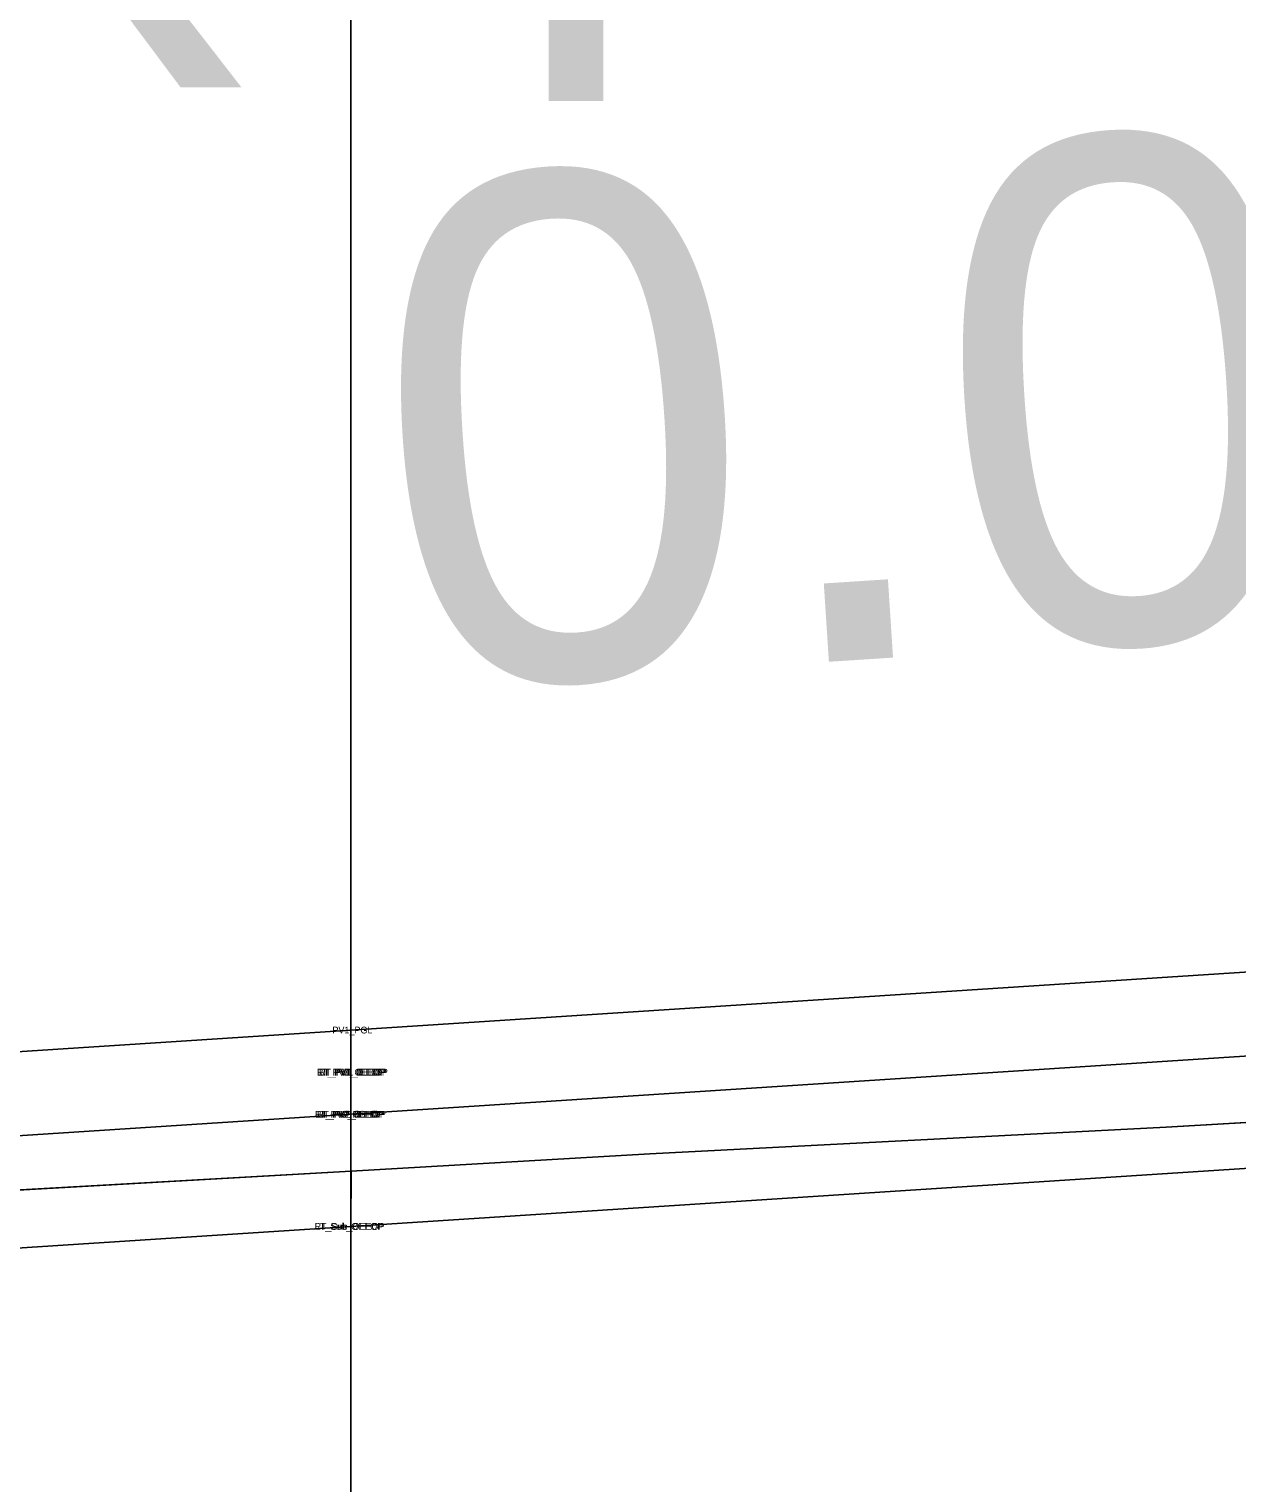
# Model space of a CAD drawing. Extents: x -26 to 403, y -376 to 1112.
# Drawn here: x 199.044 to 202.632, y 518.796 to 523.115 of the extents above; entities that cross this region are included whole.
import ezdxf

# ---------------------------------------------------------------- set-up
doc = ezdxf.new("R2010")
doc.units = 0
for name, color, linetype in [('Exist Cross Section Cell', 7, 'Continuous'), ('Exist XS Ground Line', 7, 'Continuous'), ('Prop CMT Pvmt Course 1', 7, 'Continuous'), ('Prop CMT Pvmt Course 2', 7, 'Continuous'), ('Prop CMT Pvmt Surface', 7, 'Continuous'), ('Prop CMT Subgrade Earthwork', 7, 'Continuous'), ('Prop XS Earthwork Shape', 7, 'Continuous'), ('Prop XS Roadway Elevations', 7, 'Continuous'), ('Prop XS SE Text', 7, 'Continuous'), ('Scratch_Level_0', 7, 'Continuous')]:
    doc.layers.add(name, color=color, linetype=linetype)

msp = doc.modelspace()

# ---------------------------------------------------------------- linework, layer by layer
at = {"layer": 'Exist Cross Section Cell'}
msp.add_line((200, 500), (200, 633.9199), dxfattribs=at)
at = {"layer": 'Exist XS Ground Line'}
msp.add_lwpolyline([(181.2255, 518.9624), (185.2926, 518.9145), (185.9017, 518.8726), (188.764, 519.0393), (190.6001, 519.1661), (191.7924, 519.2497), (193.5744, 519.3585), (194.565, 519.4146), (196.9434, 519.5479), (200.0001, 519.7223), (200.8881, 519.773), (202.422, 519.8526), (205.8122, 520.0509), (216.4306, 520.4665), (217.254, 520.498), (217.9663, 520.5225), (226.2164, 521.1075), (228.1595, 521.2361), (234.7331, 521.7229), (238.3527, 522.025)], dxfattribs=at)
at = {"layer": 'Prop CMT Pvmt Course 1'}
for points in [[(200, 520.1411), (205.5691, 520.5026)], [(205.5691, 520.2526), (200, 519.8911)], [(200, 520.1411), (190, 519.492)], [(200, 519.8911), (200, 520.1411)], [(200, 519.8911), (200, 520.1411)], [(190, 519.242), (200, 519.8911)]]:
    msp.add_lwpolyline(points, dxfattribs=at)
msp.add_lwpolyline([(200, 519.8911), (200, 520.0161), (200, 520.0161), (200, 519.8911)], close=True, dxfattribs=at)
msp.add_lwpolyline([(200, 519.8911), (200, 520.0161), (200, 520.0161), (200, 519.8911)], close=True, dxfattribs=at)
at = {"layer": 'Prop CMT Pvmt Course 2'}
for points in [[(200, 519.8911), (205.5691, 520.2526)], [(205.5691, 519.9193), (200, 519.5578)], [(200, 519.8911), (190, 519.242)], [(200, 519.5578), (200, 519.8911)], [(200, 519.5578), (200, 519.8911)], [(190, 518.9087), (200, 519.5578)]]:
    msp.add_lwpolyline(points, dxfattribs=at)
at = {"layer": 'Prop CMT Pvmt Surface'}
for points in [[(200, 520.1411), (205.5691, 520.5026)], [(200, 520.1411), (190, 519.492)]]:
    msp.add_lwpolyline(points, dxfattribs=at)
at = {"layer": 'Prop CMT Subgrade Earthwork'}
for points in [[(200, 519.5578), (205.5691, 519.9193)], [(200, 519.5578), (190, 518.9087)]]:
    msp.add_lwpolyline(points, dxfattribs=at)
at = {"layer": 'Prop XS Earthwork Shape'}
for points in [[(200.0001, 519.7223), (200.8881, 519.773), (202.422, 519.8526), (205.5691, 520.0367), (205.5691, 519.9193), (200, 519.5578)], [(194.565, 519.4146), (196.9434, 519.5479), (200.0001, 519.7223), (200, 519.5578), (190, 518.9087), (190, 519.1247), (190.6001, 519.1661), (191.7924, 519.2497), (193.5744, 519.3585)]]:
    msp.add_lwpolyline(points, close=True, dxfattribs=at)

# ---------------------------------------------------------------- texts
at = {"layer": 'Prop XS Roadway Elevations'}
msp.add_text('1019.14', height=1.5, rotation=90, dxfattribs=at).set_placement((200.75, 522.7487))
at = {"layer": 'Prop XS SE Text'}
msp.add_text('0.065', height=1.5, rotation=3.7139, dxfattribs=at).set_placement((200.1239, 521.1512))
at = {"layer": 'Scratch_Level_0'}
for s, p in [('PV1_PGL', (199.9448, 520.1311)), ('RT_PV1_OEEOP', (199.8983, 520.0061)), ('LT_PV1_OEEOP', (199.8988, 520.0061)), ('RT_PV1_IEEOP', (199.9048, 520.0061)), ('LT_PV1_IEEOP', (199.9052, 520.0061)), ('RT_PV2_OEEOP', (199.8926, 519.8811)), ('LT_PV2_OEEOP', (199.8931, 519.8811)), ('RT_PV2_IEEOP', (199.8991, 519.8811)), ('LT_PV2_IEEOP', (199.8996, 519.8811)), ('PV2_PGL', (199.9391, 519.8811)), ('RT_Sub_OEEOP', (199.8917, 519.5478)), ('LT_Sub_OEEOP', (199.8922, 519.5478))]:
    msp.add_text(s, height=0.02, dxfattribs=at).set_placement(p)

doc.saveas('drawing.dxf')
